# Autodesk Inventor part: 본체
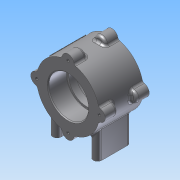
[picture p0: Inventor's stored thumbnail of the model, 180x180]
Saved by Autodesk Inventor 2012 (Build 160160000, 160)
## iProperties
Created: 2015-03
Part Number: 본체
Material: Default
Document SubType Name: Modeling
Designer: net
Density: 1 g/cm^3
Author: net
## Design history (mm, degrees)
sketch "스케치1"
  geometry: C1 r 37 at (0, 0); 1 further point
  constraints: 1 centre point, 1 coincident
  dimensions: "d0" = 37 radius of C1
extrude "돌출1" new body sketch "스케치1" distance "d1" = 52; taper "d2" = 0 deg
hole "구멍1" diameter "d5" = 47; stored, may be unused: countersink angle "d9" = 90 deg, drill point angle "d11" = 0 deg; dims "d3" = 10, "d4" = 10, "d6" = 6, "d7" = 4, "d8" = 2, "d10" = 22
hole "구멍2" diameter "d14" = 47; stored, may be unused: countersink angle "d18" = 90 deg, drill point angle "d20" = 0 deg; dims "d12" = 10, "d13" = 10, "d15" = 6, "d16" = 4, "d17" = 2, "d19" = 22
hole "구멍3" diameter "d23" = 42; stored, may be unused: countersink angle "d27" = 90 deg, drill point angle "d29" = 0 deg; dims "d21" = 10, "d22" = 10, "d24" = 6, "d25" = 4, "d26" = 2, "d28" = 22
chamfer "모따기1" distance "d30" = 1; stored, may be unused: second distance "d31" = 2, angle "d32" = 45 deg
fillet "모깎기1" dims "d33" = 0.3
sketch "스케치2"
  geometry: C1 r 7 at (0, 37); 1 further point
  constraints: 2 vertical alignment, 1 centre point, 1 other
  dimensions: "d34" = 7 radius of C1
extrude "돌출2" join sketch "스케치2" distance "d35" = 15; taper "d36" = 0 deg
hole "구멍4" diameter "d39" = 3.242; stored, may be unused: countersink angle "d43" = 90 deg, drill point angle "d45" = 118 deg; dims "d37" = 10, "d38" = 10, "d40" = 8, "d41" = 4, "d42" = 2, "d44" = 11
node "작업 평면1"
fillet "모깎기2" dims "d49" = 3
fillet "모깎기3" dims "d50" = 3
fillet "모깎기4" dims "d51" = 3
fillet "모깎기5" dims "d52" = 3
node "작업 평면2"
sketch "스케치3"
  geometry: L1 (19, -56)-(29, -56); L2 (29, -56)-(29, -21); L3 (29, -21)-(19, -21); L4 (19, -21)-(19, -56); 2 further points
  constraints: 8 end point, 1 horizontal, 1 midpoint, 1 parallel, 1 perpendicular
  dimensions: "d54" = 10 distance of L1.start L1.end; "d55" = 35 distance of L1.end L2.end; "d56" = 10 distance of L2.end L3.end; "d57" = 24 horizontal distance of point (24, -56) point (0, 0); "d58" = 56 vertical distance of L1.end point (0, 0)
extrude "돌출3" join sketch "스케치3" distance "d59" = 40; taper "d60" = 0 deg
fillet "모깎기6" dims "d61" = 5
fillet "모깎기7" dims "d62" = 3
hole "구멍5" diameter "d65" = 4.134; stored, may be unused: countersink angle "d69" = 90 deg, drill point angle "d71" = 118 deg; dims "d63" = 10, "d64" = 10, "d66" = 6, "d67" = 4, "d68" = 2, "d70" = 8
hole "구멍6" diameter "d74" = 4.134; stored, may be unused: countersink angle "d78" = 90 deg, drill point angle "d80" = 118 deg; dims "d72" = 10, "d73" = 10, "d75" = 6, "d76" = 4, "d77" = 2, "d79" = 8
hole "구멍7" diameter "d83" = 4.134; stored, may be unused: countersink angle "d87" = 90 deg, drill point angle "d89" = 118 deg; dims "d81" = 10, "d82" = 10, "d84" = 6, "d85" = 4, "d86" = 2, "d88" = 8
hole "구멍8" diameter "d92" = 4.134; stored, may be unused: countersink angle "d96" = 90 deg, drill point angle "d98" = 118 deg; dims "d90" = 10, "d91" = 10, "d93" = 6, "d94" = 4, "d95" = 2, "d97" = 8
node "작업 평면3"
sketch "스케치4"
  geometry: L1 (0, 0)-(-52.292, 0); L2 (0, 0)-(-26.163, 26.163); A1 r 37 centre (0, 0) between (-9.104, 35.863) and (-35.863, 9.104) reference
  constraints: 4 end point, 1 horizontal, 1 point on circle
  dimensions: "d99" = 45 deg angle of L1 L2
node "작업 평면4"
sketch "스케치5"
  geometry: L1 (-26, -18.921)-(-26, 18.921) reference; L2 (26, -18.921)-(26, 18.921) reference; 3 further points
  constraints: 1 horizontal alignment, 1 midpoint, 1 other
  dimensions: "d100" = 26 distance from line of L1 point (0, 0)
feature "엠보싱1" sketch "스케치5" dims "d101" = 0.5, "d102" = 0
node "솔리드1"
pattern_circular "원형 패턴1" dims angle "d47" = 360 deg
mirror "대칭1"
mirror "대칭2"
other parameters: "d53" = 6
